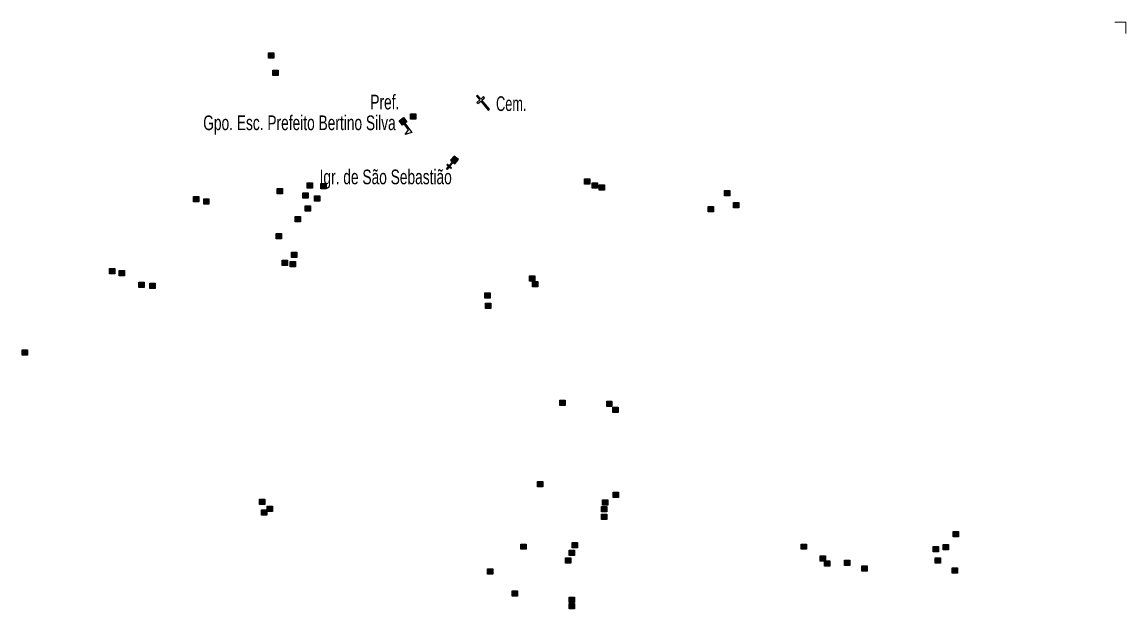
# Model space of a CAD drawing. Extents: x 647.8 to 672.9, y 6929.3 to 6957.3.
# Drawn here: x 666.85 to 672.87, y 6953.76 to 6956.95 of the extents above; entities that cross this region are included whole.
import ezdxf
from ezdxf.enums import TextEntityAlignment as Align

# ---------------------------------------------------------------- set-up
doc = ezdxf.new("R2010")
doc.units = 0
doc.header["$LTSCALE"] = 0.032
for name, color, linetype, lineweight in [('2', 7, 'Continuous', 25), ('20', 7, 'Continuous', 25), ('4', 7, 'Continuous', 25), ('6', 7, 'Continuous', 25), ('63', 7, 'Continuous', 13)]:
    doc.layers.add(name, color=color, linetype=linetype, lineweight=lineweight)
doc.layers.add('61', color=7, linetype='Continuous')

msp = doc.modelspace()

# ---------------------------------------------------------------- hatches: boundary and pattern name
at = {"layer": '2'}
for points in [[(668.1961, 6956.787), (668.2251, 6956.787), (668.2251, 6956.758), (668.1961, 6956.758)], [(668.2202, 6956.6926), (668.2492, 6956.6926), (668.2492, 6956.6636), (668.2202, 6956.6636)], [(668.9705, 6956.4535), (668.9995, 6956.4535), (668.9995, 6956.4245), (668.9705, 6956.4245)], [(668.4067, 6956.0783), (668.4357, 6956.0783), (668.4357, 6956.0493), (668.4067, 6956.0493)], [(668.4813, 6956.074), (668.5103, 6956.074), (668.5103, 6956.045), (668.4813, 6956.045)], [(669.9182, 6956.1003), (669.9472, 6956.1003), (669.9472, 6956.0713), (669.9182, 6956.0713)], [(669.9599, 6956.0783), (669.9889, 6956.0783), (669.9889, 6956.0493), (669.9599, 6956.0493)], [(669.9972, 6956.0674), (670.0262, 6956.0674), (670.0262, 6956.0384), (669.9972, 6956.0384)], [(667.788, 6956.0038), (667.817, 6956.0038), (667.817, 6955.9748), (667.788, 6955.9748)], [(668.2443, 6956.0476), (668.2733, 6956.0476), (668.2733, 6956.0186), (668.2443, 6956.0186)], [(668.3825, 6956.0235), (668.4115, 6956.0235), (668.4115, 6955.9945), (668.3825, 6955.9945)], [(668.4462, 6956.0081), (668.4752, 6956.0081), (668.4752, 6955.9791), (668.4462, 6955.9791)], [(670.6817, 6956.0367), (670.7107, 6956.0367), (670.7107, 6956.0077), (670.6817, 6956.0077)], [(667.8429, 6955.9906), (667.8719, 6955.9906), (667.8719, 6955.9616), (667.8429, 6955.9616)], [(668.3957, 6955.9533), (668.4247, 6955.9533), (668.4247, 6955.9243), (668.3957, 6955.9243)], [(670.5918, 6955.9489), (670.6208, 6955.9489), (670.6208, 6955.9199), (670.5918, 6955.9199)], [(670.73, 6955.9708), (670.759, 6955.9708), (670.759, 6955.9418), (670.73, 6955.9418)], [(668.3409, 6955.8941), (668.3699, 6955.8941), (668.3699, 6955.8651), (668.3409, 6955.8651)], [(668.2378, 6955.8019), (668.2668, 6955.8019), (668.2668, 6955.7729), (668.2378, 6955.7729)], [(668.3211, 6955.701), (668.3501, 6955.701), (668.3501, 6955.672), (668.3211, 6955.672)], [(668.2707, 6955.6571), (668.2997, 6955.6571), (668.2997, 6955.6281), (668.2707, 6955.6281)], [(668.3145, 6955.6505), (668.3435, 6955.6505), (668.3435, 6955.6215), (668.3145, 6955.6215)], [(667.3295, 6955.6111), (667.3585, 6955.6111), (667.3585, 6955.5821), (667.3295, 6955.5821)], [(667.3822, 6955.6001), (667.4112, 6955.6001), (667.4112, 6955.5711), (667.3822, 6955.5711)], [(669.6177, 6955.5716), (669.6467, 6955.5716), (669.6467, 6955.5426), (669.6177, 6955.5426)], [(667.4897, 6955.5365), (667.5187, 6955.5365), (667.5187, 6955.5075), (667.4897, 6955.5075)], [(667.5489, 6955.5321), (667.5779, 6955.5321), (667.5779, 6955.5031), (667.5489, 6955.5031)], [(669.6352, 6955.5409), (669.6642, 6955.5409), (669.6642, 6955.5119), (669.6352, 6955.5119)], [(669.3742, 6955.4794), (669.4032, 6955.4794), (669.4032, 6955.4504), (669.3742, 6955.4504)], [(669.3786, 6955.4224), (669.4076, 6955.4224), (669.4076, 6955.3934), (669.3786, 6955.3934)], [(666.8534, 6955.1679), (666.8824, 6955.1679), (666.8824, 6955.1389), (666.8534, 6955.1389)], [(669.7844, 6954.8937), (669.8134, 6954.8937), (669.8134, 6954.8647), (669.7844, 6954.8647)], [(670.0389, 6954.8893), (670.0679, 6954.8893), (670.0679, 6954.8603), (670.0389, 6954.8603)], [(670.0718, 6954.8564), (670.1008, 6954.8564), (670.1008, 6954.8274), (670.0718, 6954.8274)], [(669.6616, 6954.4505), (669.6906, 6954.4505), (669.6906, 6954.4215), (669.6616, 6954.4215)], [(670.074, 6954.3935), (670.103, 6954.3935), (670.103, 6954.3645), (670.074, 6954.3645)], [(668.1478, 6954.354), (668.1768, 6954.354), (668.1768, 6954.325), (668.1478, 6954.325)], [(668.1895, 6954.3167), (668.2185, 6954.3167), (668.2185, 6954.2877), (668.1895, 6954.2877)], [(670.0104, 6954.3145), (670.0394, 6954.3145), (670.0394, 6954.2855), (670.0104, 6954.2855)], [(670.017, 6954.3518), (670.046, 6954.3518), (670.046, 6954.3228), (670.017, 6954.3228)], [(668.1588, 6954.2969), (668.1878, 6954.2969), (668.1878, 6954.2679), (668.1588, 6954.2679)], [(670.0104, 6954.2728), (670.0394, 6954.2728), (670.0394, 6954.2438), (670.0104, 6954.2438)], [(671.9278, 6954.1785), (671.9568, 6954.1785), (671.9568, 6954.1495), (671.9278, 6954.1495)], [(669.5716, 6954.1105), (669.6006, 6954.1105), (669.6006, 6954.0815), (669.5716, 6954.0815)], [(669.8349, 6954.0776), (669.8639, 6954.0776), (669.8639, 6954.0486), (669.8349, 6954.0486)], [(669.8502, 6954.1192), (669.8792, 6954.1192), (669.8792, 6954.0902), (669.8502, 6954.0902)], [(671.0985, 6954.1105), (671.1275, 6954.1105), (671.1275, 6954.0815), (671.0985, 6954.0815)], [(671.8181, 6954.0973), (671.8471, 6954.0973), (671.8471, 6954.0683), (671.8181, 6954.0683)], [(671.873, 6954.1083), (671.902, 6954.1083), (671.902, 6954.0793), (671.873, 6954.0793)], [(669.8151, 6954.0359), (669.8441, 6954.0359), (669.8441, 6954.0069), (669.8151, 6954.0069)], [(671.2016, 6954.0468), (671.2306, 6954.0468), (671.2306, 6954.0178), (671.2016, 6954.0178)], [(671.2258, 6954.0183), (671.2548, 6954.0183), (671.2548, 6953.9893), (671.2258, 6953.9893)], [(671.3355, 6954.0227), (671.3645, 6954.0227), (671.3645, 6953.9937), (671.3355, 6953.9937)], [(671.8291, 6954.0359), (671.8581, 6954.0359), (671.8581, 6954.0069), (671.8291, 6954.0069)], [(669.3895, 6953.9744), (669.4185, 6953.9744), (669.4185, 6953.9454), (669.3895, 6953.9454)], [(671.4298, 6953.992), (671.4588, 6953.992), (671.4588, 6953.963), (671.4298, 6953.963)], [(671.9212, 6953.981), (671.9502, 6953.981), (671.9502, 6953.952), (671.9212, 6953.952)], [(669.5233, 6953.856), (669.5523, 6953.856), (669.5523, 6953.827), (669.5233, 6953.827)], [(669.8349, 6953.8209), (669.8639, 6953.8209), (669.8639, 6953.7919), (669.8349, 6953.7919)], [(669.8349, 6953.7858), (669.8639, 6953.7858), (669.8639, 6953.7568), (669.8349, 6953.7568)]]:
    msp.add_hatch(color=256, dxfattribs=at).paths.add_polyline_path(points)
at = {"layer": '4'}
msp.add_hatch(color=256, dxfattribs=at).paths.add_polyline_path([(668.9324, 6956.4342), (668.9499, 6956.4099), (668.9256, 6956.3923), (668.908, 6956.4167)])
at = {"layer": '6'}
for points in [[(669.198, 6956.1929), (669.2018, 6956.1897), (669.1842, 6956.1686), (669.1937, 6956.1606), (669.1905, 6956.1567), (669.1809, 6956.1647), (669.1697, 6956.1513), (669.1659, 6956.1546), (669.1771, 6956.168), (669.1675, 6956.176), (669.1707, 6956.1798), (669.1803, 6956.1718)], [(669.2114, 6956.1816), (669.2307, 6956.2046), (669.2077, 6956.2239), (669.1884, 6956.2009)]]:
    msp.add_hatch(color=256, dxfattribs=at).paths.add_polyline_path(points)

# ---------------------------------------------------------------- linework, layer by layer
at = {"layer": '2'}
for points in [[(668.1961, 6956.787), (668.2251, 6956.787), (668.2251, 6956.758), (668.1961, 6956.758)], [(668.2202, 6956.6926), (668.2492, 6956.6926), (668.2492, 6956.6636), (668.2202, 6956.6636)], [(668.9705, 6956.4535), (668.9995, 6956.4535), (668.9995, 6956.4245), (668.9705, 6956.4245)], [(668.4067, 6956.0783), (668.4357, 6956.0783), (668.4357, 6956.0493), (668.4067, 6956.0493)], [(668.4813, 6956.074), (668.5103, 6956.074), (668.5103, 6956.045), (668.4813, 6956.045)], [(669.9182, 6956.1003), (669.9472, 6956.1003), (669.9472, 6956.0713), (669.9182, 6956.0713)], [(669.9599, 6956.0783), (669.9889, 6956.0783), (669.9889, 6956.0493), (669.9599, 6956.0493)], [(669.9972, 6956.0674), (670.0262, 6956.0674), (670.0262, 6956.0384), (669.9972, 6956.0384)], [(667.788, 6956.0038), (667.817, 6956.0038), (667.817, 6955.9748), (667.788, 6955.9748)], [(668.2443, 6956.0476), (668.2733, 6956.0476), (668.2733, 6956.0186), (668.2443, 6956.0186)], [(668.3825, 6956.0235), (668.4115, 6956.0235), (668.4115, 6955.9945), (668.3825, 6955.9945)], [(668.4462, 6956.0081), (668.4752, 6956.0081), (668.4752, 6955.9791), (668.4462, 6955.9791)], [(670.6817, 6956.0367), (670.7107, 6956.0367), (670.7107, 6956.0077), (670.6817, 6956.0077)], [(667.8429, 6955.9906), (667.8719, 6955.9906), (667.8719, 6955.9616), (667.8429, 6955.9616)], [(668.3957, 6955.9533), (668.4247, 6955.9533), (668.4247, 6955.9243), (668.3957, 6955.9243)], [(670.5918, 6955.9489), (670.6208, 6955.9489), (670.6208, 6955.9199), (670.5918, 6955.9199)], [(670.73, 6955.9708), (670.759, 6955.9708), (670.759, 6955.9418), (670.73, 6955.9418)], [(668.3409, 6955.8941), (668.3699, 6955.8941), (668.3699, 6955.8651), (668.3409, 6955.8651)], [(668.2378, 6955.8019), (668.2668, 6955.8019), (668.2668, 6955.7729), (668.2378, 6955.7729)], [(668.3211, 6955.701), (668.3501, 6955.701), (668.3501, 6955.672), (668.3211, 6955.672)], [(668.2707, 6955.6571), (668.2997, 6955.6571), (668.2997, 6955.6281), (668.2707, 6955.6281)], [(668.3145, 6955.6505), (668.3435, 6955.6505), (668.3435, 6955.6215), (668.3145, 6955.6215)], [(667.3295, 6955.6111), (667.3585, 6955.6111), (667.3585, 6955.5821), (667.3295, 6955.5821)], [(667.3822, 6955.6001), (667.4112, 6955.6001), (667.4112, 6955.5711), (667.3822, 6955.5711)], [(669.6177, 6955.5716), (669.6467, 6955.5716), (669.6467, 6955.5426), (669.6177, 6955.5426)], [(667.4897, 6955.5365), (667.5187, 6955.5365), (667.5187, 6955.5075), (667.4897, 6955.5075)], [(667.5489, 6955.5321), (667.5779, 6955.5321), (667.5779, 6955.5031), (667.5489, 6955.5031)], [(669.6352, 6955.5409), (669.6642, 6955.5409), (669.6642, 6955.5119), (669.6352, 6955.5119)], [(669.3742, 6955.4794), (669.4032, 6955.4794), (669.4032, 6955.4504), (669.3742, 6955.4504)], [(669.3786, 6955.4224), (669.4076, 6955.4224), (669.4076, 6955.3934), (669.3786, 6955.3934)], [(666.8534, 6955.1679), (666.8824, 6955.1679), (666.8824, 6955.1389), (666.8534, 6955.1389)], [(669.7844, 6954.8937), (669.8134, 6954.8937), (669.8134, 6954.8647), (669.7844, 6954.8647)], [(670.0389, 6954.8893), (670.0679, 6954.8893), (670.0679, 6954.8603), (670.0389, 6954.8603)], [(670.0718, 6954.8564), (670.1008, 6954.8564), (670.1008, 6954.8274), (670.0718, 6954.8274)], [(669.6616, 6954.4505), (669.6906, 6954.4505), (669.6906, 6954.4215), (669.6616, 6954.4215)], [(670.074, 6954.3935), (670.103, 6954.3935), (670.103, 6954.3645), (670.074, 6954.3645)], [(668.1478, 6954.354), (668.1768, 6954.354), (668.1768, 6954.325), (668.1478, 6954.325)], [(668.1895, 6954.3167), (668.2185, 6954.3167), (668.2185, 6954.2877), (668.1895, 6954.2877)], [(670.0104, 6954.3145), (670.0394, 6954.3145), (670.0394, 6954.2855), (670.0104, 6954.2855)], [(670.017, 6954.3518), (670.046, 6954.3518), (670.046, 6954.3228), (670.017, 6954.3228)], [(668.1588, 6954.2969), (668.1878, 6954.2969), (668.1878, 6954.2679), (668.1588, 6954.2679)], [(670.0104, 6954.2728), (670.0394, 6954.2728), (670.0394, 6954.2438), (670.0104, 6954.2438)], [(671.9278, 6954.1785), (671.9568, 6954.1785), (671.9568, 6954.1495), (671.9278, 6954.1495)], [(669.5716, 6954.1105), (669.6006, 6954.1105), (669.6006, 6954.0815), (669.5716, 6954.0815)], [(669.8349, 6954.0776), (669.8639, 6954.0776), (669.8639, 6954.0486), (669.8349, 6954.0486)], [(669.8502, 6954.1192), (669.8792, 6954.1192), (669.8792, 6954.0902), (669.8502, 6954.0902)], [(671.0985, 6954.1105), (671.1275, 6954.1105), (671.1275, 6954.0815), (671.0985, 6954.0815)], [(671.8181, 6954.0973), (671.8471, 6954.0973), (671.8471, 6954.0683), (671.8181, 6954.0683)], [(671.873, 6954.1083), (671.902, 6954.1083), (671.902, 6954.0793), (671.873, 6954.0793)], [(669.8151, 6954.0359), (669.8441, 6954.0359), (669.8441, 6954.0069), (669.8151, 6954.0069)], [(671.2016, 6954.0468), (671.2306, 6954.0468), (671.2306, 6954.0178), (671.2016, 6954.0178)], [(671.2258, 6954.0183), (671.2548, 6954.0183), (671.2548, 6953.9893), (671.2258, 6953.9893)], [(671.3355, 6954.0227), (671.3645, 6954.0227), (671.3645, 6953.9937), (671.3355, 6953.9937)], [(671.8291, 6954.0359), (671.8581, 6954.0359), (671.8581, 6954.0069), (671.8291, 6954.0069)], [(669.3895, 6953.9744), (669.4185, 6953.9744), (669.4185, 6953.9454), (669.3895, 6953.9454)], [(671.4298, 6953.992), (671.4588, 6953.992), (671.4588, 6953.963), (671.4298, 6953.963)], [(671.9212, 6953.981), (671.9502, 6953.981), (671.9502, 6953.952), (671.9212, 6953.952)], [(669.5233, 6953.856), (669.5523, 6953.856), (669.5523, 6953.827), (669.5233, 6953.827)], [(669.8349, 6953.8209), (669.8639, 6953.8209), (669.8639, 6953.7919), (669.8349, 6953.7919)], [(669.8349, 6953.7858), (669.8639, 6953.7858), (669.8639, 6953.7568), (669.8349, 6953.7568)]]:
    msp.add_lwpolyline(points, close=True, dxfattribs=at)
at = {"layer": '20'}
for points in [[(669.3532, 6956.5349), (669.3352, 6956.5563), (669.3291, 6956.5511), (669.3471, 6956.5298)], [(669.3587, 6956.5284), (669.374, 6956.5413), (669.3685, 6956.5478), (669.3532, 6956.5349)], [(669.3471, 6956.5298), (669.3318, 6956.5168), (669.3373, 6956.5104), (669.3526, 6956.5233), (669.3936, 6956.4747)], [(669.3936, 6956.4747), (669.3997, 6956.4799), (669.3587, 6956.5284)]]:
    msp.add_lwpolyline(points, dxfattribs=at)
at = {"layer": '4'}
msp.add_line((668.9398, 6956.4026), (668.9357, 6956.3996), dxfattribs=at)
for points in [[(668.9324, 6956.4342), (668.9499, 6956.4099), (668.9256, 6956.3923), (668.908, 6956.4167)], [(668.9398, 6956.4026), (668.9763, 6956.3518), (668.9406, 6956.3415), (668.9588, 6956.3676), (668.9357, 6956.3996)]]:
    msp.add_lwpolyline(points, close=True, dxfattribs=at)
at = {"layer": '6'}
for points in [[(669.198, 6956.1929), (669.2018, 6956.1897), (669.1842, 6956.1686), (669.1937, 6956.1606), (669.1905, 6956.1567), (669.1809, 6956.1647), (669.1697, 6956.1513), (669.1659, 6956.1546), (669.1771, 6956.168), (669.1675, 6956.176), (669.1707, 6956.1798), (669.1803, 6956.1718)], [(669.2114, 6956.1816), (669.2307, 6956.2046), (669.2077, 6956.2239), (669.1884, 6956.2009)]]:
    msp.add_lwpolyline(points, close=True, dxfattribs=at)
at = {"layer": '63'}
msp.add_lwpolyline([(672.8683, 6956.8925), (672.8683, 6956.9541), (672.8076, 6956.9541)], dxfattribs=at)

# ---------------------------------------------------------------- texts
at = {"layer": '61', "width": 0.7}
for s, p in [('Pref.', (668.9092, 6956.4783)), ('Gpo. Esc. Prefeito Bertino Silva', (668.8893, 6956.3654)), ('Igr. de São Sebastião', (669.1949, 6956.0705))]:
    msp.add_text(s, height=0.08, dxfattribs=at).set_placement(p, align=Align.RIGHT)
at = {"layer": '61', "width": 0.65}
msp.add_text('Cem.', height=0.08, dxfattribs=at).set_placement((669.4361, 6956.4696))

doc.saveas('drawing.dxf')
